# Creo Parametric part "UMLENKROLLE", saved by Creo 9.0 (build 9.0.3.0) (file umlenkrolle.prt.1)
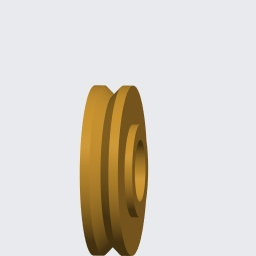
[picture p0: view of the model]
Units: millimeter Kilogram Sec (mmKs); MM, KILOGRAM, SECS
Materials in the file: STAHL

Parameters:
  WERKSTOFF = "Stahl"
  ERSTELLER = "ARINDA"
  BENENNUNG = "XXX"
  TEILETYP = "K"
  PTC_MASTER_MATERIAL = "STAHL"

Other parameters: MASSE

Created from: ARINDA_STARTTEIL.PRT

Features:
  1. coordinate system
  2. datum plane "RECHTS_Y-Z"
  3. datum plane "OBEN_X-Z"
  4. datum plane "VORNE_X-Y"
  5. datum axis
  6. datum axis
  7. datum axis
  8. datum point "PNT0"
  9. revolve "Drehen 1"
  10. extrusion "Profil 1"

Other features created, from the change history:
  coordinate system "CS1"
  component interface "Komponentenschnittstelle ID 108"

Other named items: UMLENKROLLE, LOGO, A_X, A_Y, A_Z, CS0

Layers: 01_ACHSEN_STD, 01_EBENEN_STD, 01_KOORDSYS_STD, 01_PUNKTE_STD, VOLUMENGEOMETRIE

Surfaces: 92 plane, 8 cylinder, 4 cone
